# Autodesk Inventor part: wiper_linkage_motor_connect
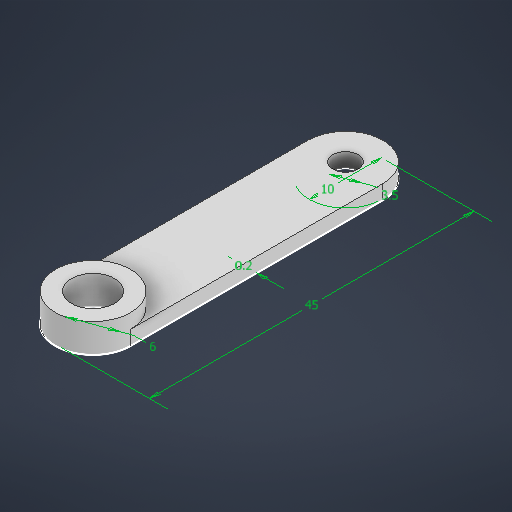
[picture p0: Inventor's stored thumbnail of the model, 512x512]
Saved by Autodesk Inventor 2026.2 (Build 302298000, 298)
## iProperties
Created: 2026-03
Part Number: wiper_linkage_motor_connect
Material: Generic
Document SubType Name: Modeling
Designer: Tathagata Sikdar
Density: 1 g/cm^3
Appearance: Default
Author: Tathagata Sikdar
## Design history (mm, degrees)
sketch "Sketch1"
  geometry: L1 (0, 0)-(0, -45); L2 (-5, -5)-(-5, -40); L3 (5, -40)-(5, -5); L4 (-5.2, -40)-(-5.2, -5); L5 (5.2, -5)-(5.2, -40); C1 r 3 at (0, -5); C2 r 1.75 at (0, -40); C3 r 5.2 at (0, -5); A1 r 5 centre (0, -5) between (5, -5) and (-5, -5); A2 r 5 centre (0, -40) between (-5, -40) and (5, -40); A3 r 5.2 centre (0, -5) between (5.2, -5) and (-5.2, -5); A4 r 5.2 centre (0, -40) between (-5.2, -40) and (5.2, -40); 5 further points
  constraints: 12 end point, 10 point on circle, 7 centre point, 5 tangent, 3 coincident, 2 parallel, 2 point on line, 1 midpoint, 1 vertical, 3 other
  dimensions: "d0" = 45 distance of L1.start L1.end; "d1" = 10 diameter of A2; "d2" = 0.2 distance between parallel lines of L2 L4; "d3" = 6 diameter of C1; "d4" = 3.5 diameter of C2
extrude "Extrusion1" new body sketch "Sketch1" distance "d5" = 2; taper "d6" = 0 deg
extrude "Extrusion2" join sketch "Sketch1" distance "d7" = 4; taper "d8" = 0 deg
body "Solid1"
